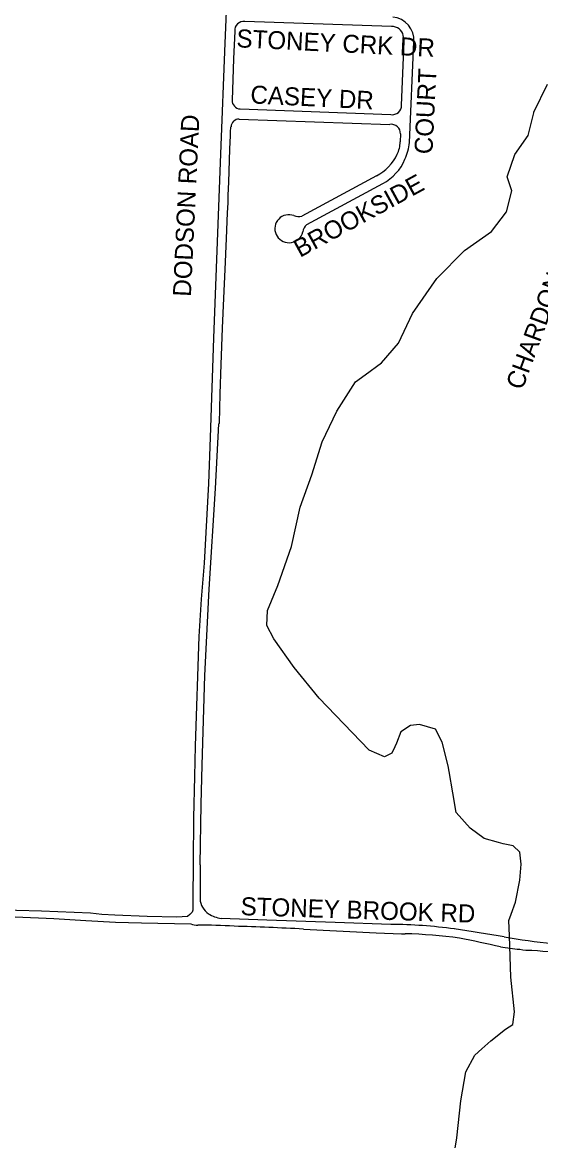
# Model space of a CAD drawing. Extents: x 0 to 712119, y 0 to 761125.
# Drawn here: x 664320 to 665756, y 728717 to 731817 of the extents above; entities that cross this region are included whole.
import ezdxf

# ---------------------------------------------------------------- set-up
doc = ezdxf.new("R2010")
doc.units = 0
for name, color, linetype in [('PAVED ROADS', 7, 'Continuous'), ('stream or creek', 7, 'Continuous'), ('street names', 7, 'Continuous')]:
    doc.layers.add(name, color=color, linetype=linetype)

msp = doc.modelspace()

# ---------------------------------------------------------------- linework, layer by layer
at = {"layer": 'PAVED ROADS'}
for points in [[(664897.5, 732157.7), (664881.5, 731759.5), (664869.6, 731451.9), (664857, 731135.2), (664849.9, 730940.9), (664840.3, 730665.6), (664835.7, 730538.1), (664823.5, 730317.5), (664815.5, 730218), (664809.5, 730114), (664799.1, 729811.1), (664797.1, 729726.4), (664794.7, 729611.9), (664793.5, 729487.5), (664792.3, 729383.4), (664792.7, 729363.8), (664792.7, 729356.2), (664790.3, 729350.5), (664784.4, 729343.4), (664778, 729338.3), (664747.8, 729336.7), (664666.1, 729337.9), (664576.9, 729342.1), (664540.2, 729343.7), (664508.8, 729347.4), (664373.7, 729353.4), (664234.1, 729357)], [(665343.1, 731804.9), (664936.9, 731819.3)], [(664908.5, 731791.9), (664905.4, 731715.7), (664901.1, 731601.4)], [(665370.8, 731587.3), (665377.5, 731763.6)], [(665392.4, 731483.7), (665404.9, 731763.1)], [(664920.8, 731548.8), (665338, 731534)], [(664923.8, 731576.7), (665340.8, 731561)], [(664813.2, 729481.8), (664815.9, 729649.3), (664818.5, 729757.6), (664825.9, 730006.7), (664838, 730245.8), (664855, 730525), (664864.3, 730703.6), (664866.1, 730705.9), (664868.7, 730787.5), (664871.3, 730868), (664875.1, 730969.3), (664878.7, 731052.2), (664882.3, 731132), (664885.4, 731217.2), (664889, 731289), (664890, 731316.9), (664890.3, 731337.7), (664891.9, 731373.9), (664895.4, 731465.7), (664896.8, 731503.2), (664897.2, 731509.4), (664897.3, 731512.7), (664898.2, 731527.6)], [(665367.7, 731507.3), (665367, 731485.2)], [(665301.2, 731391.1), (665094.8, 731279.2)], [(665108, 731256), (665318.5, 731370)], [(664300.8, 729337), (664407.9, 729332.5), (664496.1, 729327.4), (664578, 729322.8), (664650.6, 729320.9), (664787.3, 729318)], [(665341, 729316.5), (665186.5, 729321.5), (664997.5, 729328.5), (664871, 729333)], [(665099.4, 729303.3), (665300.1, 729293.3), (665370.5, 729290.3), (665380.7, 729290.4)]]:
    msp.add_lwpolyline(points, dxfattribs=at)
for centre, radius, start, end in [((665341.3, 731767.5), 63.8, 356.0253, 85.5939), ((664933.7, 731794.2), 25.3, 82.8534, 185.1583), ((665345.6, 731774.8), 30.2, 9.7741, 94.8255), ((665322.1, 731764.7), 55.4, 358.8288, 15.8943), ((664925.8, 731601.3), 24.7, 179.849, 265.3734), ((665344.6, 731586.9), 26.1, 261.5486, 0.9699), ((664921.2, 731525.8), 23, 90.9236, 175.6771), ((665341.4, 731507.9), 26.4, 358.8397, 97.3288), ((665287, 731486.9), 80, 333.3537, 358.8256), ((665257.3, 731494.4), 135.5, 335.102, 355.4557), ((665240.1, 731507), 131, 297.8228, 334.6947), ((665256.9, 731488.5), 133.5, 297.4669, 337.4891), ((665058.5, 731244.8), 38.8, 68.8226, 271.5103), ((665086.7, 731318.2), 39.8, 249.0485, 281.6368), ((665131.6, 731229.8), 35.3, 132.0659, 169.0792), ((665060.4, 731243.2), 37.2, 268.6693, 349.5759), ((668110.1, 729411.2), 3297.7, 178.7731, 180.4203), ((664865.4, 729390.1), 53, 183.353, 236.2871), ((664802.4, 729347.4), 33.1, 242.7334, 276.8793), ((664885.8, 729426.6), 94.8, 238.2626, 260.9846), ((664783.9, 727114.4), 2200.3, 86.7993, 89.4153), ((664667.3, 721206.6), 8108.2, 86.94499, 88.30726), ((665325.7, 727866.4), 1450.2, 82.4241, 89.3944), ((665349.7, 727934.9), 1355.8, 82.3141, 88.6913), ((664388.6, 721686.1), 7700.9, 80.5327, 81.57506), ((664027.9, 722056.5), 7376.9, 77.33816, 78.24247), ((665946.1, 730884.7), 1628.7, 259.7159, 264.4453), ((665774.5, 730077.3), 833.5, 261.0537, 264.7302), ((665723.7, 729374.8), 130.1, 258.5643, 273.5491), ((665922, 731232.3), 1996.4, 264.5315, 268.0042)]:
    msp.add_arc(centre, radius, start, end, dxfattribs=at)
at = {"layer": 'stream or creek'}
msp.add_lwpolyline([(665503.5, 728601.1), (665523.9, 728724.5), (665534.8, 728827.6), (665548.9, 728907.3), (665573.9, 728954.2), (665592.8, 728971.1), (665617.6, 728993.3), (665658.3, 729026.1), (665679.1, 729038.9), (665683.1, 729073.9), (665673.1, 729169.9), (665670.1, 729284.9), (665668.1, 729326.9), (665674.4, 729344.9), (665686.1, 729377.9), (665698.1, 729438.9), (665702.1, 729482.9), (665698.1, 729516.9), (665680.1, 729533.9), (665652.1, 729539.9), (665638.9, 729543.6), (665599.1, 729554.9), (665561.1, 729582.9), (665522.1, 729626.9), (665513.1, 729680.9), (665502.9, 729740), (665500.1, 729755.9), (665483.1, 729821.9), (665465.1, 729857.9), (665420.1, 729870.9), (665395.1, 729867.9), (665369.1, 729849.9), (665357.1, 729818.9), (665352.4, 729808.7), (665344.1, 729790.9), (665323.1, 729780.9), (665281.1, 729798.9), (665211.1, 729871.9), (665142.1, 729943.9), (665073.1, 730028.9), (665017.1, 730107.9), (664997.1, 730144.9), (664999.1, 730186.9), (665028.1, 730255.9), (665066.1, 730363.9), (665090.1, 730472.9), (665122.1, 730562.9), (665151.1, 730653.9), (665191.6, 730738.8), (665242.7, 730819.9), (665269.7, 730839.5), (665314.9, 730872.6), (665362.5, 730927.2), (665401.2, 731010), (665468.1, 731106.8), (665545.5, 731184.3), (665619.5, 731237.1), (665661.8, 731291.7), (665675.8, 731349.8), (665663.5, 731388.6), (665684.7, 731450.2), (665721.6, 731503), (665737, 731566), (665737.5, 731568.2), (665774.5, 731645.7)], dxfattribs=at)

# ---------------------------------------------------------------- texts
at = {"layer": 'street names'}
for s, rotation, p in [('STONEY CRK DR', 357.1923, (664912.5, 731747.9)), ('COURT', 87.1923, (665456, 731450.4)), ('CASEY DR', 357.1923, (664951.1, 731592.3)), ('DODSON ROAD', 87.2823, (664787.1, 731055.5)), ('CHARDONNAY COURT', 69.8517, (665705.2, 730795.1)), ('BROOKSIDE', 28.6942, (665089.4, 731163.8)), ('STONEY BROOK RD', 358.1398, (664924.4, 729342.1))]:
    msp.add_text(s, height=50, rotation=rotation, dxfattribs=at).set_placement(p)

doc.saveas('drawing.dxf')
